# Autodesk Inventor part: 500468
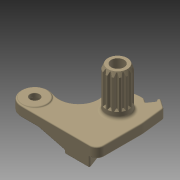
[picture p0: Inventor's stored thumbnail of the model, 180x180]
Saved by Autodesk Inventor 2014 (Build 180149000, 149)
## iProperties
Created: 2007-11
Part Number: 500468
Document SubType Name: Modeling
Designer: TH
Density: 1.32 g/cm^3
Mass: 22.8369 g
Surface Area: 82.2825 cm^2
Volume: 17.3007 cm^3
Material: Polyaryletherketone Resin
Description: BELL CRANK SIDE HANDLE
Appearance: Wheat
Component Category: Side Component
Author: TH
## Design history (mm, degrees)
sketch "Sketch1"
  geometry: L1 (-33.767, -12.195)-(-30.377, -13.071); L2 (-59.423, 0)-(29.185, 0) reference; L3 (16.5, 0)-(16.5, -30.893); L4 (-36.143, -30.893)-(16.5, -30.893); L5 (14.646, 17.212)-(7.786, 22.016); L6 (14.646, 17.212)-(16.394, 1.868); L7 (7.786, 22.016)-(6.639, 20.377); L8 (6.639, 20.377)-(8.277, 19.23); L9 (8.277, 19.23)-(4.835, 14.315); L10 (1.867, 16.394)-(4.835, 14.315); A1 r 9.5 centre (-36.143, -21.393) between (-33.767, -12.195) and (-36.143, -30.893); A2 r 13.5 centre (-27, 0) between (-30.377, -13.071) and (-15.167, 6.498); A3 r 16.5 centre (0, 0) between (16.5, 0) and (16.394, 1.868); A4 r 16.5 centre (0, 0) between (1.867, 16.394) and (-15.167, 6.498); 2 further points
  constraints: 18 end point, 8 point on circle, 5 perpendicular, 5 tangent, 4 centre point, 2 coincident, 1 parallel, 1 point on line
  dimensions: "d0" = 36.1433 horizontal distance of point (0, 0) point (-36.143, -21.393); "d1" = 21.39306 vertical distance of point (-36.143, -21.393) point (0, 0); "d3" = 19 diameter of A1; "d4" = 27 diameter of A2; "d5" = 27 distance of point (0, 0) A2.centre; "d6" = 35 deg angle of L2 L5; "d7" = 22.5 distance from line of L5 point (0, 0); "d8" = 6.5 deg angle of L6 L3; "d9" = 4.25 distance from line of L9 point (0, 0); "d10" = 20.5 distance from line of point (0, 0) L8; "d11" = 2 distance between parallel lines of L9 L7; "d12" = 16.5 radius of A3; "d13" = 16.5 radius of A4; "d14" = 6 distance between parallel lines of L10 L8
extrude "Extrusion1" new body sketch "Sketch1" distance "d15" = 7; taper "d16" = 0 deg
fillet "Fillet1" dims "d17" = 7
fillet "Fillet2" dims "d18" = 0.5
fillet "Fillet3" dims "d19" = 1
fillet "Fillet4" dims "d20" = 2
fillet "Fillet5" dims "d21" = 5
sketch "Sketch2"
  geometry: C1 r 8.5 at (-36.143, -21.393); A1 r 9.5 centre (-36.143, -21.393) between (-33.767, -12.195) and (-36.143, -30.893) reference
  constraints: 1 centre point, 1 coincident
  dimensions: "d22" = 17 diameter of C1
extrude "Extrusion2" join sketch "Sketch2" distance "d23" = 0.7; taper "d24" = 0 deg
fillet "Fillet6" dims "d25" = 0.75
sketch "Sketch3" dims "d17" = 7
  geometry: L1 (36.143, -30.893)-(-11.5, -30.893) reference; L2 (3.73, -18.333)-(6.285, -30.893); L3 (-6.919, -18.507)-(-11.55, -30.893); L4 (-6.919, -18.507)-(3.73, -18.333); L5 (0, -42.639)-(0, 32.333) reference; L6 (-30.171, 0)-(58.279, 0) reference; L7 (5.675, -27.893)-(24.25, -27.893); L8 (24.25, -27.893)-(24.25, -30.893); A1 r 5 centre (-11.5, -25.893) between (-16.5, -25.893) and (-11.5, -30.893) reference; A2 r 16.5 centre (0, 0) between (12.833, 10.371) and (-1.309, 16.448) reference
  constraints: 10 end point, 3 point on line, 2 perpendicular, 1 point on circle
  dimensions: "d26" = 0.934279 deg angle of L6 L4; "d27" = 11.5002 deg angle of L5 L2; "d28" = 20.4998 deg angle of L5 L3; "d29" = 18.5069 distance from line of L6 L3.start; "d30" = 18.33323 distance from line of L6 L2.start; "d31" = 3.72997 distance from line of L5 L2.start; "d32" = 24.25 distance from line of A2.centre L8; "d33" = 3 distance between parallel lines of L1 L7
extrude "Extrusion3" join sketch "Sketch3" distance "d34" = 6.775; taper "d35" = 0 deg
sketch "Sketch7"
  geometry: L1 (24.25, -30.893)-(-11.5, -30.893) reference; L2 (24.25, -27.893)-(24.25, -30.893) reference; L3 (5.675, -27.893)-(24.25, -27.893) reference; L4 (3.73, -18.333)-(5.675, -27.893) reference; L5 (5.675, -27.893)-(6.285, -30.893); 1 further point
  constraints: 2 end point, 1 collinear, 1 point on line
extrude "Extrusion4" cut sketch "Sketch7" distance "d48" = 2; taper "d49" = 0 deg
chamfer "Chamfer1" distance "d50" = 4.775; stored, may be unused: second distance "d51" = 18.575, angle "d52" = 45 deg
fillet "Fillet7" dims "d53" = 0.75
fillet "Fillet8" dims "d54" = 0.75
fillet "Fillet9" dims "d55" = 0.75
fillet "Fillet10" dims "d56" = 0.75
fillet "Fillet11" dims "d57" = 0.75
sketch "Sketch8"
  geometry: C1 r 8.02 at (0, 0); A1 r 15.75 centre (0, 0) between (1.249, 15.7) and (-12.25, 9.899) reference
  constraints: 1 centre point, 1 coincident
  dimensions: "d58" = 16.04 diameter of C1
extrude "Extrusion5" join sketch "Sketch8" distance "d59" = 28; taper "d60" = 0 deg
sketch "Sketch9"
  geometry: C1 r 6.75 at (36.143, -21.393); A1 r 8.75 centre (36.143, -21.393) between (36.143, -30.143) and (33.955, -12.921) reference
  constraints: 1 centre point, 1 coincident
  dimensions: "d61" = 13.5 diameter of C1
extrude "Extrusion6" cut sketch "Sketch9" distance "d62" = 4.9; taper "d63" = 0 deg
sketch "Sketch10"
  geometry: C1 r 3.225 at (36.143, -21.393); A1 r 8.75 centre (36.143, -21.393) between (36.143, -30.143) and (33.955, -12.921) reference
  constraints: 1 centre point, 1 coincident
  dimensions: "d64" = 6.45 diameter of C1
extrude "Extrusion7" cut sketch "Sketch10" stored distance "d65" = 5.475; taper "d66" = 0 deg
fillet "Fillet12" dims "d67" = 0.75
fillet "Fillet13" dims "d68" = 0.25
sketch "Sketch11"
  geometry: L1 (-30.893, -13.025)-(-30.893, -0.75) reference; L2 (-30.143, 0)-(-8.02, 0) reference; L3 (-8.02, 0)-(-8.02, 28) reference; L4 (-8.02, 28)-(8.02, 28) reference; L5 (8.02, 28)-(8.02, 0) reference; L6 (8.02, 0)-(15.75, 0) reference; L7 (16.5, -0.75)-(16.5, -6.25) reference; L8 (15.75, -7)-(-17.644, -7) reference; L9 (-18.394, -7.75)-(-18.394, -13.025) reference; L10 (-19.144, -13.775)-(-30.143, -13.775) reference; L11 (6.72, 28)-(8.02, 25); L12 (8.02, 25)-(8.02, 28); L13 (6.72, 28)-(8.02, 28); L14 (0, -21.266)-(0, 29.211) reference; A1 r 0.75 centre (-30.143, -13.025) between (-30.893, -13.025) and (-30.143, -13.775) reference; A2 r 0.75 centre (-30.143, -0.75) between (-30.143, 0) and (-30.893, -0.75) reference; A3 r 0.75 centre (15.75, -0.75) between (16.5, -0.75) and (15.75, 0) reference; A4 r 0.75 centre (15.75, -6.25) between (15.75, -7) and (16.5, -6.25) reference; 3 further points; 2 other entities
  constraints: 6 end point, 2 collinear, 2 point on line, 2 other
  dimensions: "d70" = 3 vertical distance of L11.start L11.end; "d79" = 1.3 distance from line of L5 L11.start
revolve "Revolution1" sketch "Sketch11" stored, may be unused: angle "d71" = 90 deg
sketch "Sketch12"
  geometry: C1 r 6.72 at (0, 0) reference; C2 r 4.5 at (0, 0)
  constraints: 1 centre point, 1 coincident
  dimensions: "d72" = 9 diameter of C2
extrude "Extrusion8" cut sketch "Sketch12" stored distance "d73" = 5.475; taper "d74" = 0 deg
sketch "Sketch13"
  geometry: C1 r 8.25 at (0, 0); A1 r 15.75 centre (0, 0) between (-15.649, 1.783) and (-15.75, 0) reference
  constraints: 1 centre point, 1 coincident
  dimensions: "d75" = 16.5 diameter of C1
extrude "Extrusion9" cut sketch "Sketch13" distance "d76" = 1; taper "d77" = 0 deg
fillet "Fillet14" dims "d78" = 0.5
fillet "Fillet17" dims "d100" = 0.8
sketch "Sketch15"
  geometry: L1 (0, 0)-(-9.4, -13.425); L2 (7.703, 18.411)-(5.122, 14.725) reference; L3 (5.122, 14.725)-(7.703, 18.411) reference; L4 (0, 0)-(-9.995, -6.005); L5 (-6.147, -5.152)-(-5.84, -3.859); L6 (-7.434, -3.009)-(-6.149, -3.345); A1 r 8.02 centre (0, 0) between (-6.147, -5.152) and (-7.434, -3.009) reference; A2 r 7 centre (0, 0) between (-6.149, -3.345) and (-5.84, -3.859)
  constraints: 8 end point, 4 point on circle, 1 centre point, 1 coincident, 1 parallel
  dimensions: "d80" = 0.3 distance from line of L4 L6.end; "d81" = 0.3 distance from line of L4 L5.end (= d80); "d82" = 1.25 distance from line of L4 L6.start; "d83" = 1.25 distance from line of L4 L5.start (= d82); "d93" = 24 deg angle of L1 L4; "d103" = 7 radius of A2
extrude "Extrusion10" cut sketch "Sketch15" distance "d84" = 23.5; taper "d85" = 0 deg
pattern_circular "Circular Pattern2" dims angle "d91" = 312 deg
sketch "Sketch16"
  geometry: L1 (0, -0.9)-(0, 5.4) reference; L2 (-8.02, 0)-(8.02, 0) reference; L3 (-25.893, 0)-(-30.143, 0) reference; L4 (0, 0)-(-25.893, 0) reference; L5 (1.783, 0)-(0, 0) reference; L6 (16.232, 0)-(1.783, 0) reference; L7 (17.115, 0)-(16.232, 0) reference; L8 (20.828, 0)-(17.115, 0) reference; L9 (20.418, 0)-(20.828, 0) reference; L10 (17.981, 0)-(20.418, 0) reference; L11 (14.295, 0)-(17.981, 0) reference; L12 (13.988, 0)-(14.295, 0) reference; L13 (15.478, 0)-(13.988, 0) reference; L14 (15.7, 0)-(15.478, 0) reference; L15 (9.899, 0)-(15.7, 0) reference; L16 (4.151, 0)-(9.899, 0) reference; L17 (-13.797, 0)-(4.151, 0) reference; L18 (-13.67, 0)-(-13.797, 0) reference; L19 (-30.143, 0)-(-13.67, 0) reference; L20 (5.02, 0)-(5.02, 8.5); L21 (5.02, 8.5)-(8.02, 4.5); L22 (8.02, 4.5)-(8.02, 0); L23 (8.02, 0)-(5.02, 0)
  constraints: 8 end point, 2 perpendicular, 2 point on line, 1 parallel
  dimensions: "d94" = 16.04 diameter of L22 L1; "d95" = 3 distance between parallel lines of L22 L20; "d96" = 4.5 distance of L21.end L22.end; "d97" = 8.5 distance of L20.start L20.end
revolve "Revolution2" sketch "Sketch16" stored, may be unused: angle "d98" = 90 deg
fillet "Fillet16" dims "d99" = 2
fillet "Fillet18" dims "d101" = 0.2
fillet "Fillet19" dims "d102" = 0.2
body "Solid1"
node "Projected Loop2"
node "Projected Loop3"
node "Projected Loop4"
node "Project Cut Edges1"
other parameters: "d2" = 33
